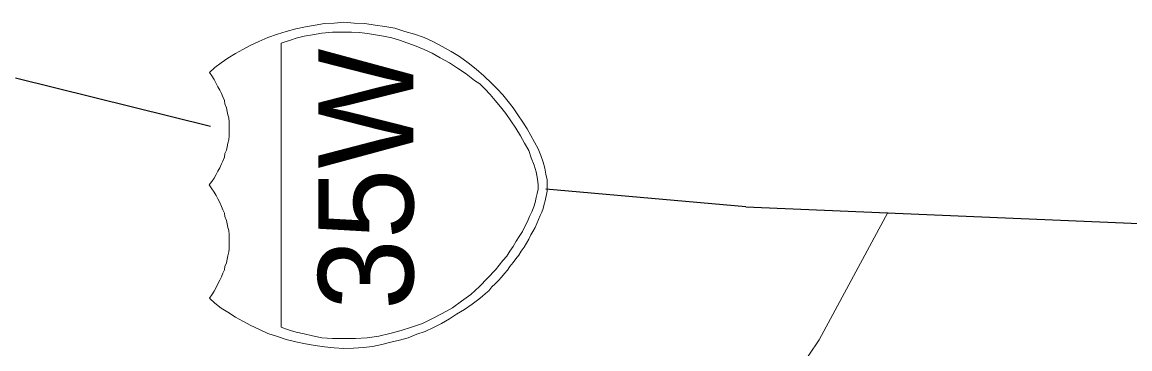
# Model space of a CAD drawing. Extents: x 2363323 to 2367082, y 6956018 to 6980837.
# Drawn here: x 2365875.6 to 2365935, y 6956829.6 to 6956847.2 of the extents above; entities that cross this region are included whole.
import ezdxf

# ---------------------------------------------------------------- set-up
doc = ezdxf.new("R2010")
doc.units = 0
doc.header["$LTSCALE"] = 4.1
doc.layers.add('62', color=7, linetype='Continuous', lineweight=13)
doc.layers.add('63', color=7, linetype='Continuous', lineweight=13)

msp = doc.modelspace()

# ---------------------------------------------------------------- linework, layer by layer
at = {"layer": '62', "lineweight": 25}
for p, q in [((2365875.243, 6956844.162), (2365885.703, 6956841.573)), ((2365914.394, 6956837.253), (2365903.684, 6956838.2))]:
    msp.add_line(p, q, dxfattribs=at)
at = {"layer": '62'}
for points in [[(2365886.089, 6956839.166), (2365886.201, 6956839.347), (2365886.291, 6956839.55), (2365886.361, 6956839.706), (2365886.451, 6956839.908), (2365886.471, 6956840.11), (2365886.561, 6956840.29), (2365886.585, 6956840.47), (2365886.631, 6956840.672), (2365886.675, 6956840.852), (2365886.697, 6956841.056), (2365886.698, 6956841.236), (2365886.697, 6956841.438), (2365886.697, 6956841.618), (2365886.697, 6956841.798), (2365886.674, 6956842.022), (2365886.631, 6956842.18), (2365886.585, 6956842.36), (2365886.561, 6956842.564), (2365886.471, 6956842.766), (2365886.451, 6956842.947), (2365886.359, 6956843.15), (2365886.291, 6956843.33), (2365886.201, 6956843.51), (2365886.089, 6956843.691), (2365885.999, 6956843.871), (2365885.887, 6956844.072), (2365885.773, 6956844.274), (2365885.637, 6956844.453), (2365885.933, 6956844.724), (2365886.269, 6956844.974), (2365886.629, 6956845.22), (2365887.035, 6956845.467), (2365887.441, 6956845.692), (2365887.867, 6956845.918), (2365888.294, 6956846.12), (2365888.768, 6956846.324), (2365889.284, 6956846.504), (2365889.757, 6956846.66), (2365890.274, 6956846.794), (2365890.791, 6956846.908), (2365891.309, 6956846.997), (2365891.804, 6956847.087), (2365892.321, 6956847.11), (2365892.839, 6956847.156), (2365893.403, 6956847.11), (2365893.965, 6956847.087), (2365894.527, 6956846.997), (2365895.043, 6956846.93), (2365895.585, 6956846.84), (2365896.124, 6956846.66), (2365896.643, 6956846.504), (2365897.159, 6956846.324), (2365897.655, 6956846.097), (2365898.127, 6956845.851), (2365898.599, 6956845.58), (2365899.049, 6956845.31), (2365899.521, 6956844.972), (2365899.949, 6956844.634), (2365900.355, 6956844.274), (2365900.781, 6956843.871), (2365901.075, 6956843.577), (2365901.367, 6956843.262), (2365901.661, 6956842.902), (2365901.929, 6956842.562), (2365902.177, 6956842.18), (2365902.447, 6956841.798), (2365902.671, 6956841.438), (2365902.875, 6956841.078), (2365903.077, 6956840.718), (2365903.257, 6956840.358), (2365903.415, 6956840), (2365903.527, 6956839.638), (2365903.618, 6956839.322), (2365903.685, 6956839.008), (2365903.751, 6956838.694), (2365903.753, 6956838.423)], [(2365903.753, 6956838.423), (2365903.753, 6956838.243), (2365903.751, 6956838.086), (2365903.707, 6956837.907), (2365903.684, 6956837.748), (2365903.639, 6956837.568), (2365903.594, 6956837.388), (2365903.528, 6956837.163), (2365903.459, 6956836.962), (2365903.369, 6956836.78), (2365903.279, 6956836.578), (2365903.189, 6956836.353), (2365903.099, 6956836.15), (2365902.987, 6956835.927), (2365902.874, 6956835.746), (2365902.761, 6956835.52), (2365902.649, 6956835.297), (2365902.515, 6956835.093), (2365902.357, 6956834.87), (2365902.221, 6956834.666), (2365902.065, 6956834.464), (2365901.931, 6956834.26), (2365901.751, 6956834.056), (2365901.614, 6956833.854), (2365901.458, 6956833.674), (2365901.299, 6956833.472), (2365901.143, 6956833.292), (2365900.963, 6956833.112), (2365900.781, 6956832.956), (2365900.625, 6956832.752), (2365900.444, 6956832.594), (2365900.287, 6956832.459), (2365900.085, 6956832.302), (2365899.724, 6956832.032), (2365899.321, 6956831.739), (2365898.891, 6956831.493), (2365898.509, 6956831.242), (2365898.081, 6956830.996), (2365897.655, 6956830.773), (2365897.205, 6956830.569), (2365896.754, 6956830.412), (2365896.305, 6956830.232), (2365895.831, 6956830.095), (2365895.361, 6956829.984), (2365894.887, 6956829.872), (2365894.393, 6956829.76), (2365893.898, 6956829.714), (2365893.357, 6956829.669), (2365892.839, 6956829.646), (2365892.321, 6956829.692), (2365891.805, 6956829.738), (2365891.309, 6956829.806), (2365890.791, 6956829.894), (2365890.274, 6956830.006), (2365889.758, 6956830.142), (2365889.284, 6956830.299), (2365888.767, 6956830.456), (2365888.295, 6956830.682), (2365887.868, 6956830.882), (2365887.441, 6956831.109), (2365887.034, 6956831.334), (2365886.631, 6956831.604), (2365886.269, 6956831.808), (2365885.931, 6956832.076), (2365885.639, 6956832.346), (2365885.773, 6956832.528), (2365885.887, 6956832.73), (2365885.999, 6956832.932), (2365886.091, 6956833.112), (2365886.201, 6956833.314), (2365886.291, 6956833.494), (2365886.361, 6956833.696), (2365886.451, 6956833.876), (2365886.473, 6956834.055), (2365886.561, 6956834.238), (2365886.584, 6956834.44), (2365886.629, 6956834.62), (2365886.674, 6956834.844), (2365886.698, 6956835.003), (2365886.697, 6956835.184), (2365886.698, 6956835.408), (2365886.698, 6956835.586), (2365886.698, 6956835.768), (2365886.675, 6956835.972), (2365886.631, 6956836.15), (2365886.584, 6956836.33), (2365886.561, 6956836.51), (2365886.473, 6956836.737), (2365886.449, 6956836.916), (2365886.359, 6956837.096), (2365886.293, 6956837.276), (2365886.203, 6956837.478), (2365886.089, 6956837.68), (2365885.999, 6956837.86), (2365885.887, 6956838.042), (2365885.773, 6956838.22), (2365885.636, 6956838.423), (2365885.773, 6956838.604), (2365885.888, 6956838.782), (2365886.001, 6956838.986), (2365886.089, 6956839.166)], [(2365892.907, 6956790.696), (2365894.617, 6956791.236), (2365898.533, 6956798.008), (2365905.351, 6956806.224), (2365911.133, 6956819.433), (2365918.335, 6956830.119), (2365922.003, 6956836.938)]]:
    msp.add_lwpolyline(points, dxfattribs=at)
msp.add_lwpolyline([(2365889.488, 6956846.03), (2365889.487, 6956830.796), (2365889.713, 6956830.706), (2365889.981, 6956830.614), (2365890.298, 6956830.526), (2365890.724, 6956830.434), (2365891.175, 6956830.323), (2365891.669, 6956830.232), (2365892.231, 6956830.186), (2365892.841, 6956830.186), (2365893.471, 6956830.186), (2365894.099, 6956830.232), (2365894.729, 6956830.322), (2365895.314, 6956830.456), (2365895.92, 6956830.614), (2365896.483, 6956830.794), (2365897.069, 6956830.995), (2365897.609, 6956831.266), (2365898.128, 6956831.536), (2365898.667, 6956831.829), (2365899.161, 6956832.189), (2365899.658, 6956832.549), (2365900.129, 6956832.976), (2365900.558, 6956833.426), (2365900.984, 6956833.878), (2365901.367, 6956834.373), (2365901.591, 6956834.598), (2365901.749, 6956834.868), (2365901.929, 6956835.116), (2365902.088, 6956835.408), (2365902.245, 6956835.657), (2365902.424, 6956835.926), (2365902.559, 6956836.197), (2365902.694, 6956836.466), (2365902.808, 6956836.736), (2365902.919, 6956836.984), (2365903.031, 6956837.253), (2365903.099, 6956837.478), (2365903.167, 6956837.748), (2365903.213, 6956837.973), (2365903.257, 6956838.196), (2365903.257, 6956838.423), (2365903.234, 6956838.736), (2365903.167, 6956839.12), (2365903.053, 6956839.48), (2365902.897, 6956839.886), (2365902.761, 6956840.268), (2365902.537, 6956840.673), (2365902.311, 6956841.057), (2365902.064, 6956841.462), (2365901.794, 6956841.867), (2365901.525, 6956842.248), (2365901.255, 6956842.61), (2365900.961, 6956842.947), (2365900.691, 6956843.283), (2365900.399, 6956843.577), (2365900.131, 6956843.848), (2365899.861, 6956844.027), (2365899.409, 6956844.388), (2365898.937, 6956844.68), (2365898.507, 6956844.972), (2365898.014, 6956845.242), (2365897.587, 6956845.49), (2365897.159, 6956845.692), (2365896.731, 6956845.872), (2365896.281, 6956846.03), (2365895.833, 6956846.187), (2365895.427, 6956846.322), (2365894.977, 6956846.412), (2365894.549, 6956846.481), (2365894.121, 6956846.547), (2365893.694, 6956846.594), (2365893.267, 6956846.614), (2365892.841, 6956846.614), (2365892.233, 6956846.614), (2365891.669, 6956846.571), (2365891.175, 6956846.48), (2365890.725, 6956846.412), (2365890.298, 6956846.3), (2365889.981, 6956846.188), (2365889.711, 6956846.098)], close=True, dxfattribs=at)
at = {"layer": '62', "lineweight": 25}
msp.add_lwpolyline([(2365914.394, 6956837.253), (2365959.513, 6956835.342), (2365969.909, 6956837.184)], dxfattribs=at)
at = {"layer": '63', "lineweight": 25}
for p, q in [((2365875.243, 6956844.162), (2365885.703, 6956841.573)), ((2365914.394, 6956837.253), (2365903.684, 6956838.2))]:
    msp.add_line(p, q, dxfattribs=at)
at = {"layer": '63'}
for points in [[(2365886.089, 6956839.166), (2365886.201, 6956839.347), (2365886.291, 6956839.55), (2365886.361, 6956839.706), (2365886.451, 6956839.908), (2365886.471, 6956840.11), (2365886.561, 6956840.29), (2365886.585, 6956840.47), (2365886.631, 6956840.672), (2365886.675, 6956840.852), (2365886.697, 6956841.056), (2365886.698, 6956841.236), (2365886.697, 6956841.438), (2365886.697, 6956841.618), (2365886.697, 6956841.798), (2365886.674, 6956842.022), (2365886.631, 6956842.18), (2365886.585, 6956842.36), (2365886.561, 6956842.564), (2365886.471, 6956842.766), (2365886.451, 6956842.947), (2365886.359, 6956843.15), (2365886.291, 6956843.33), (2365886.201, 6956843.51), (2365886.089, 6956843.691), (2365885.999, 6956843.871), (2365885.887, 6956844.072), (2365885.773, 6956844.274), (2365885.637, 6956844.453), (2365885.933, 6956844.724), (2365886.269, 6956844.974), (2365886.629, 6956845.22), (2365887.035, 6956845.467), (2365887.441, 6956845.692), (2365887.867, 6956845.918), (2365888.294, 6956846.12), (2365888.768, 6956846.324), (2365889.284, 6956846.504), (2365889.757, 6956846.66), (2365890.274, 6956846.794), (2365890.791, 6956846.908), (2365891.309, 6956846.997), (2365891.804, 6956847.087), (2365892.321, 6956847.11), (2365892.839, 6956847.156), (2365893.403, 6956847.11), (2365893.965, 6956847.087), (2365894.527, 6956846.997), (2365895.043, 6956846.93), (2365895.585, 6956846.84), (2365896.124, 6956846.66), (2365896.643, 6956846.504), (2365897.159, 6956846.324), (2365897.655, 6956846.097), (2365898.127, 6956845.851), (2365898.599, 6956845.58), (2365899.049, 6956845.31), (2365899.521, 6956844.972), (2365899.949, 6956844.634), (2365900.355, 6956844.274), (2365900.781, 6956843.871), (2365901.075, 6956843.577), (2365901.367, 6956843.262), (2365901.661, 6956842.902), (2365901.929, 6956842.562), (2365902.177, 6956842.18), (2365902.447, 6956841.798), (2365902.671, 6956841.438), (2365902.875, 6956841.078), (2365903.077, 6956840.718), (2365903.257, 6956840.358), (2365903.415, 6956840), (2365903.527, 6956839.638), (2365903.618, 6956839.322), (2365903.685, 6956839.008), (2365903.751, 6956838.694), (2365903.753, 6956838.423)], [(2365903.753, 6956838.423), (2365903.753, 6956838.243), (2365903.751, 6956838.086), (2365903.707, 6956837.907), (2365903.684, 6956837.748), (2365903.639, 6956837.568), (2365903.594, 6956837.388), (2365903.528, 6956837.163), (2365903.459, 6956836.962), (2365903.369, 6956836.78), (2365903.279, 6956836.578), (2365903.189, 6956836.353), (2365903.099, 6956836.15), (2365902.987, 6956835.927), (2365902.874, 6956835.746), (2365902.761, 6956835.52), (2365902.649, 6956835.297), (2365902.515, 6956835.093), (2365902.357, 6956834.87), (2365902.221, 6956834.666), (2365902.065, 6956834.464), (2365901.931, 6956834.26), (2365901.751, 6956834.056), (2365901.614, 6956833.854), (2365901.458, 6956833.674), (2365901.299, 6956833.472), (2365901.143, 6956833.292), (2365900.963, 6956833.112), (2365900.781, 6956832.956), (2365900.625, 6956832.752), (2365900.444, 6956832.594), (2365900.287, 6956832.459), (2365900.085, 6956832.302), (2365899.724, 6956832.032), (2365899.321, 6956831.739), (2365898.891, 6956831.493), (2365898.509, 6956831.242), (2365898.081, 6956830.996), (2365897.655, 6956830.773), (2365897.205, 6956830.569), (2365896.754, 6956830.412), (2365896.305, 6956830.232), (2365895.831, 6956830.095), (2365895.361, 6956829.984), (2365894.887, 6956829.872), (2365894.393, 6956829.76), (2365893.898, 6956829.714), (2365893.357, 6956829.669), (2365892.839, 6956829.646), (2365892.321, 6956829.692), (2365891.805, 6956829.738), (2365891.309, 6956829.806), (2365890.791, 6956829.894), (2365890.274, 6956830.006), (2365889.758, 6956830.142), (2365889.284, 6956830.299), (2365888.767, 6956830.456), (2365888.295, 6956830.682), (2365887.868, 6956830.882), (2365887.441, 6956831.109), (2365887.034, 6956831.334), (2365886.631, 6956831.604), (2365886.269, 6956831.808), (2365885.931, 6956832.076), (2365885.639, 6956832.346), (2365885.773, 6956832.528), (2365885.887, 6956832.73), (2365885.999, 6956832.932), (2365886.091, 6956833.112), (2365886.201, 6956833.314), (2365886.291, 6956833.494), (2365886.361, 6956833.696), (2365886.451, 6956833.876), (2365886.473, 6956834.055), (2365886.561, 6956834.238), (2365886.584, 6956834.44), (2365886.629, 6956834.62), (2365886.674, 6956834.844), (2365886.698, 6956835.003), (2365886.697, 6956835.184), (2365886.698, 6956835.408), (2365886.698, 6956835.586), (2365886.698, 6956835.768), (2365886.675, 6956835.972), (2365886.631, 6956836.15), (2365886.584, 6956836.33), (2365886.561, 6956836.51), (2365886.473, 6956836.737), (2365886.449, 6956836.916), (2365886.359, 6956837.096), (2365886.293, 6956837.276), (2365886.203, 6956837.478), (2365886.089, 6956837.68), (2365885.999, 6956837.86), (2365885.887, 6956838.042), (2365885.773, 6956838.22), (2365885.636, 6956838.423), (2365885.773, 6956838.604), (2365885.888, 6956838.782), (2365886.001, 6956838.986), (2365886.089, 6956839.166)], [(2365892.907, 6956790.696), (2365894.617, 6956791.236), (2365898.533, 6956798.008), (2365905.351, 6956806.224), (2365911.133, 6956819.433), (2365918.335, 6956830.119), (2365922.003, 6956836.938)]]:
    msp.add_lwpolyline(points, dxfattribs=at)
msp.add_lwpolyline([(2365889.488, 6956846.03), (2365889.487, 6956830.796), (2365889.713, 6956830.706), (2365889.981, 6956830.614), (2365890.298, 6956830.526), (2365890.724, 6956830.434), (2365891.175, 6956830.323), (2365891.669, 6956830.232), (2365892.231, 6956830.186), (2365892.841, 6956830.186), (2365893.471, 6956830.186), (2365894.099, 6956830.232), (2365894.729, 6956830.322), (2365895.314, 6956830.456), (2365895.92, 6956830.614), (2365896.483, 6956830.794), (2365897.069, 6956830.995), (2365897.609, 6956831.266), (2365898.128, 6956831.536), (2365898.667, 6956831.829), (2365899.161, 6956832.189), (2365899.658, 6956832.549), (2365900.129, 6956832.976), (2365900.558, 6956833.426), (2365900.984, 6956833.878), (2365901.367, 6956834.373), (2365901.591, 6956834.598), (2365901.749, 6956834.868), (2365901.929, 6956835.116), (2365902.088, 6956835.408), (2365902.245, 6956835.657), (2365902.424, 6956835.926), (2365902.559, 6956836.197), (2365902.694, 6956836.466), (2365902.808, 6956836.736), (2365902.919, 6956836.984), (2365903.031, 6956837.253), (2365903.099, 6956837.478), (2365903.167, 6956837.748), (2365903.213, 6956837.973), (2365903.257, 6956838.196), (2365903.257, 6956838.423), (2365903.234, 6956838.736), (2365903.167, 6956839.12), (2365903.053, 6956839.48), (2365902.897, 6956839.886), (2365902.761, 6956840.268), (2365902.537, 6956840.673), (2365902.311, 6956841.057), (2365902.064, 6956841.462), (2365901.794, 6956841.867), (2365901.525, 6956842.248), (2365901.255, 6956842.61), (2365900.961, 6956842.947), (2365900.691, 6956843.283), (2365900.399, 6956843.577), (2365900.131, 6956843.848), (2365899.861, 6956844.027), (2365899.409, 6956844.388), (2365898.937, 6956844.68), (2365898.507, 6956844.972), (2365898.014, 6956845.242), (2365897.587, 6956845.49), (2365897.159, 6956845.692), (2365896.731, 6956845.872), (2365896.281, 6956846.03), (2365895.833, 6956846.187), (2365895.427, 6956846.322), (2365894.977, 6956846.412), (2365894.549, 6956846.481), (2365894.121, 6956846.547), (2365893.694, 6956846.594), (2365893.267, 6956846.614), (2365892.841, 6956846.614), (2365892.233, 6956846.614), (2365891.669, 6956846.571), (2365891.175, 6956846.48), (2365890.725, 6956846.412), (2365890.298, 6956846.3), (2365889.981, 6956846.188), (2365889.711, 6956846.098)], close=True, dxfattribs=at)
at = {"layer": '63', "lineweight": 25}
msp.add_lwpolyline([(2365914.394, 6956837.253), (2365959.513, 6956835.342), (2365969.909, 6956837.184)], dxfattribs=at)

# ---------------------------------------------------------------- texts
at = {"layer": '62'}
msp.add_text('35W', height=5.099, rotation=90, dxfattribs=at).set_placement((2365896.573, 6956831.719))
at = {"layer": '63'}
msp.add_text('35W', height=5.099, rotation=90, dxfattribs=at).set_placement((2365896.573, 6956831.719))

doc.saveas('drawing.dxf')
